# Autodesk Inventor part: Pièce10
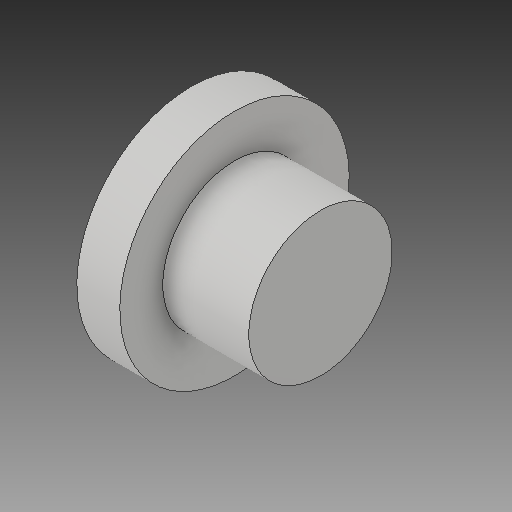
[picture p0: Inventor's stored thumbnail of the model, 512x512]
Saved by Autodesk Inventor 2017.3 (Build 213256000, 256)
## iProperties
Created: 2007-11
Part Number: Pièce10
Material: Générique
Document SubType Name: Modeling
Designer: ficho
Density: 1 g/cm^3
Appearance: Par défaut
Author: ficho
Sending System: SolidWorks 2009
Last Author: christophe
Last Saved: 2011-02-10
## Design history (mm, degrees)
feature "Révolution1"
node "Solide1"
